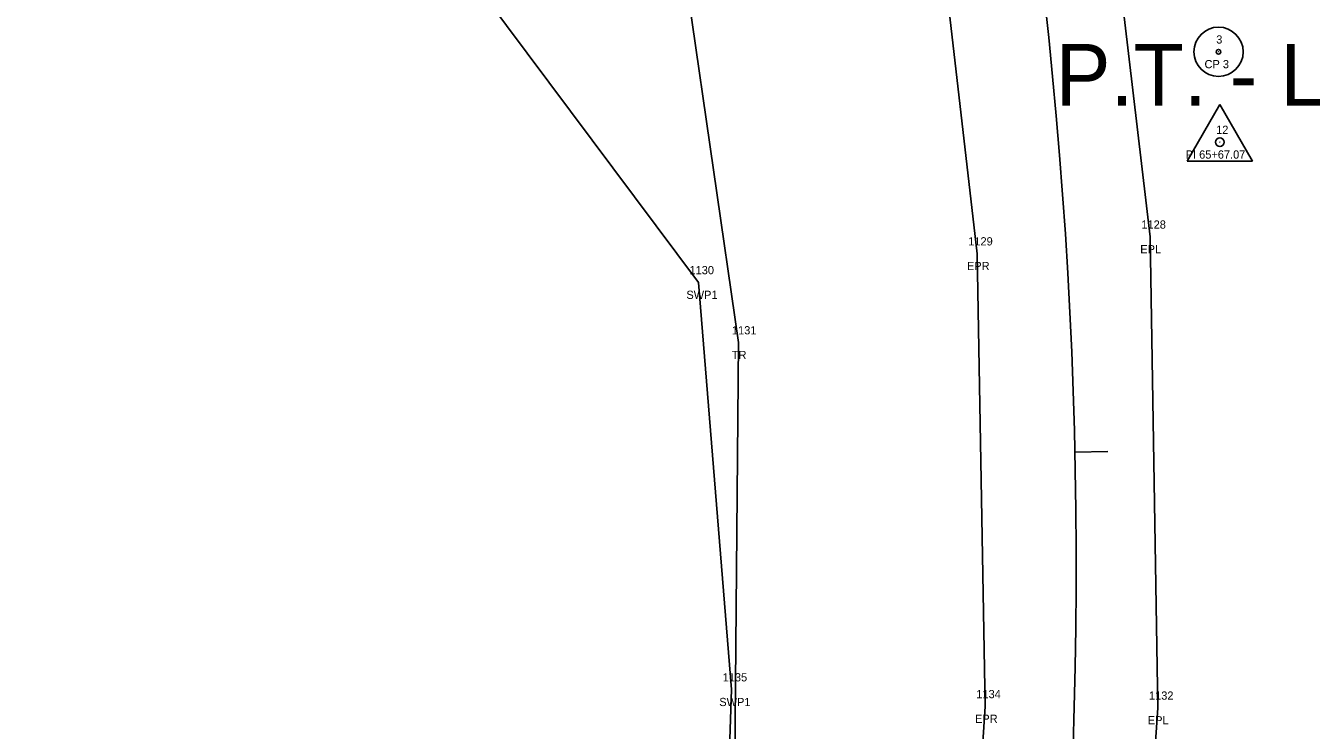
# Model space of a CAD drawing. Extents: x 2432632 to 2433497, y 684847 to 688233.
# Drawn here: x 2433028.9 to 2433185.1, y 686210.1 to 686295.7 of the extents above; entities that cross this region are included whole.
import ezdxf

# ---------------------------------------------------------------- set-up
doc = ezdxf.new("R2010")
doc.units = 0
for name, color, linetype in [('RD_EX_H2O', 7, 'Continuous'), ('RD_EX_H2O_txCode', 7, 'Continuous'), ('RD_EX_Road', 7, 'Continuous'), ('RD_EX_Road_txCode', 7, 'Continuous'), ('RD_EX_VEG', 7, 'Continuous'), ('RD_EX_VEG_txCode', 7, 'Continuous'), ('RD_HC_Cl', 7, 'Continuous'), ('RD_HC_Data', 7, 'Continuous'), ('RD_HC_Data_Tic', 7, 'Continuous'), ('RD_HC_txCode', 7, 'Continuous'), ('RD_SMD_Locator', 7, 'Continuous')]:
    doc.layers.add(name, color=color, linetype=linetype)

msp = doc.modelspace()

# ---------------------------------------------------------------- linework, layer by layer
at = {"layer": 'RD_EX_H2O'}
msp.add_lwpolyline([(2433059.53, 686447.22), (2433075.46, 686410.47), (2433059.4, 686367.42), (2433076.9, 686309.73), (2433110.63, 686264.52), (2433114.63, 686215.04), (2433113.03, 686166.79), (2433114.46, 686111.82), (2433110.48, 686084.68), (2433120.95, 686072.12)], dxfattribs=at)
at = {"layer": 'RD_EX_Road'}
for points in [[(2433066.06, 686565.78), (2433098.73, 686469.74), (2433113.88, 686422.91), (2433127.93, 686372.14), (2433139.1, 686314.76), (2433144.47, 686268.02), (2433145.44, 686213), (2433142.32, 686164.92), (2433135.44, 686115.75), (2433128.09, 686081.14)], [(2433088.99, 686562.5), (2433099.45, 686534.09), (2433118.26, 686478), (2433133.83, 686430.29), (2433148.35, 686377.56), (2433159.33, 686322.19), (2433165.5, 686270.06), (2433166.43, 686212.82), (2433163.02, 686162.81), (2433156.19, 686111.14), (2433152.88, 686076.43)]]:
    msp.add_lwpolyline(points, dxfattribs=at)
at = {"layer": 'RD_EX_VEG'}
msp.add_lwpolyline([(2433112.43, 688094.61), (2433041.17, 687898.89), (2432988.9, 687699.78), (2432947.96, 687578.08), (2432935.9, 687556.87), (2432944.3, 687538.7), (2432913.88, 687397.98), (2432902.4, 687330.02), (2432885.78, 687157.56), (2432894.43, 687032.93), (2432918.07, 686924.4), (2432974.73, 686759.54), (2433073.82, 686456.42), (2433099.9, 686365.23), (2433115.47, 686257.21), (2433114.64, 686158.77), (2433095.68, 686092.78)], dxfattribs=at)
at = {"layer": 'RD_HC_Cl'}
msp.add_arc((2432536.11, 686229.97), 620.41, 350.43349, 18.81644, dxfattribs=at)
at = {"layer": 'RD_HC_Data'}
for p, q in [((2433170, 686279.28), (2433173.97, 686286.16)), ((2433173.97, 686286.16), (2433177.94, 686279.28)), ((2433170, 686279.28), (2433177.94, 686279.28))]:
    msp.add_line(p, q, dxfattribs=at)
for centre, radius in [((2433173.81, 686292.55), 3), ((2433173.81, 686292.55), 0.282), ((2433173.97, 686281.57), 0.529)]:
    msp.add_circle(centre, radius, dxfattribs=at)
at = {"layer": 'RD_HC_Data_Tic'}
msp.add_line((2433156.37, 686243.9), (2433160.37, 686243.99), dxfattribs=at)
at = {"layer": 'RD_SMD_Locator'}
for centre in [(2433173.81, 686292.55), (2433173.97, 686281.57), (2433165.5, 686270.06), (2433144.47, 686268.02), (2433110.63, 686264.52), (2433115.47, 686257.21), (2433114.63, 686215.04), (2433145.44, 686213), (2433166.43, 686212.82)]:
    msp.add_circle(centre, 0.001, dxfattribs=at)

# ---------------------------------------------------------------- texts
at = {"layer": 'RD_EX_H2O_txCode'}
for s, p in [('1130', (2433109.53, 686265.52)), ('SWP1', (2433109.15, 686262.52)), ('1135', (2433113.56, 686216.04)), ('SWP1', (2433113.15, 686213.04))]:
    msp.add_text(s, height=1, dxfattribs=at).set_placement(p)
at = {"layer": 'RD_EX_Road_txCode'}
for s, p in [('1128', (2433164.44, 686271.06)), ('1129', (2433143.4, 686269.02)), ('EPL', (2433164.3, 686268.06)), ('EPR', (2433143.24, 686266.02)), ('1134', (2433144.38, 686214)), ('1132', (2433165.36, 686213.82)), ('EPR', (2433144.22, 686211)), ('EPL', (2433165.22, 686210.82))]:
    msp.add_text(s, height=1, dxfattribs=at).set_placement(p)
at = {"layer": 'RD_EX_VEG_txCode'}
for s, p in [('1131', (2433114.69, 686258.21)), ('TR', (2433114.67, 686255.21))]:
    msp.add_text(s, height=1, dxfattribs=at).set_placement(p)
at = {"layer": 'RD_HC_Data'}
msp.add_text('P.T. - LG% = ', height=7.5, dxfattribs=at).set_placement((2433154, 686286))
at = {"layer": 'RD_HC_txCode'}
for s, p in [('3', (2433173.53, 686293.55)), ('CP 3', (2433172.11, 686290.55)), ('12', (2433173.52, 686282.57)), ('PI 65+67.07', (2433169.82, 686279.57))]:
    msp.add_text(s, height=1, dxfattribs=at).set_placement(p)

doc.saveas('drawing.dxf')
